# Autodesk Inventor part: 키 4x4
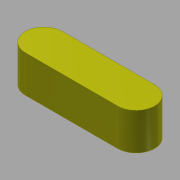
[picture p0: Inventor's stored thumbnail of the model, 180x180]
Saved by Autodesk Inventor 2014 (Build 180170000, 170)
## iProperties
Created: 2014-10
Part Number: 키 4x4
Document SubType Name: Modeling
Designer: KYOUNG IL JANG
Density: 7.86 g/cm^3
Mass: 1.65269 g
Surface Area: 2.35398 cm^2
Volume: 0.210265 cm^3
Material: 강철, 연강
Appearance: 노란색
Author: SeoGD™ [www.esajin.kr]
Revision Number: 1
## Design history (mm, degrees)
sketch "스케치1"
  geometry: L1 (-5, -2)-(5, -2); L2 (5, 2)-(-5, 2); A1 r 2 centre (5, 0) between (5, -2) and (5, 2); A2 r 2 centre (-5, 0) between (-5, 2) and (-5, -2); 2 further points
  constraints: 4 end point, 4 point on circle, 4 tangent, 2 centre point, 1 horizontal, 1 horizontal alignment, 1 midpoint, 1 parallel, 1 vertical alignment
  dimensions: "d0" = 4 distance between parallel lines of L1 L2; "d1" = 14 dimension on A1 A2
extrude "돌출1" new body sketch "스케치1" stored distance "d2" = 4; taper "d3" = 0 deg
node "솔리드1"
